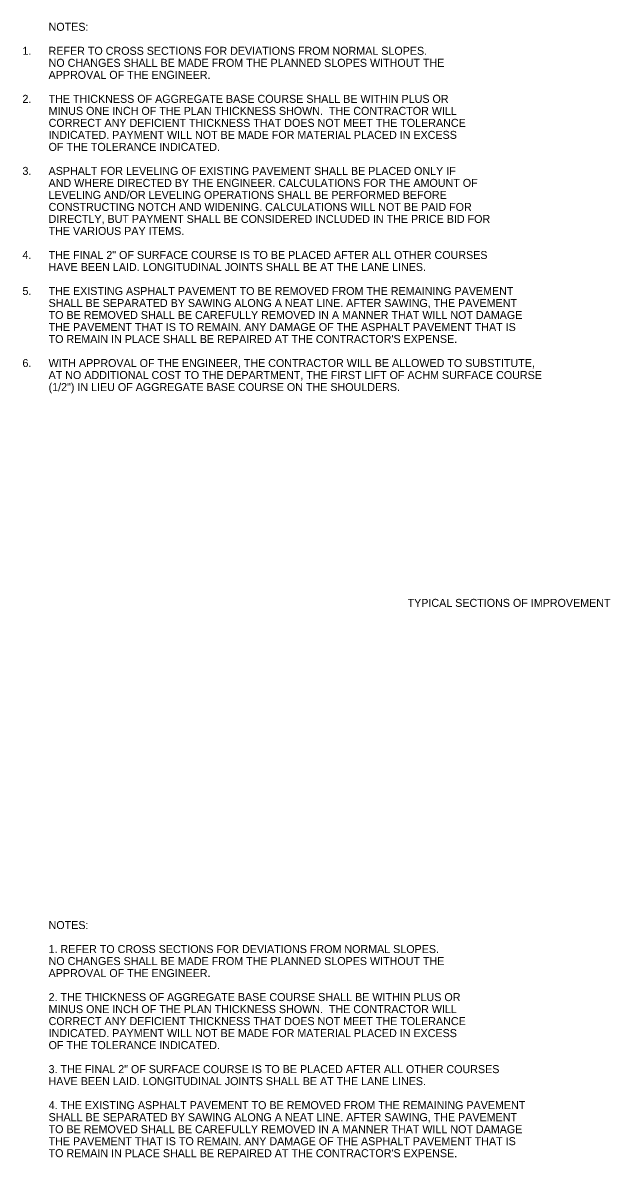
# Model space of a CAD drawing. Extents: x 138 to 3619, y -519 to 1449.
# Drawn here: x 1197 to 1637, y 598 to 1449 of the extents above; entities that cross this region are included whole.
import ezdxf

# ---------------------------------------------------------------- set-up
doc = ezdxf.new("R2010")
doc.units = 0
doc.layers.add('R_Annotation', color=7, linetype='Continuous')
doc.layers.add('R_Border', color=7, linetype='Continuous')

msp = doc.modelspace()

# ---------------------------------------------------------------- texts
at = {"layer": 'R_Annotation'}
for s, p in [('NOTES:', (1216.67, 1442.52)), ('1.', (1197.09, 1424.52)), ('REFER TO CROSS SECTIONS FOR DEVIATIONS FROM NORMAL SLOPES. ', (1216.67, 1424.52)), ('NO CHANGES SHALL BE MADE FROM THE PLANNED SLOPES WITHOUT THE', (1216.67, 1415.52)), ('APPROVAL OF THE ENGINEER.', (1216.67, 1406.52)), ('2.', (1197.09, 1388.52)), ('THE THICKNESS OF AGGREGATE BASE COURSE SHALL BE WITHIN PLUS OR', (1216.67, 1388.52)), ('MINUS ONE INCH OF THE PLAN THICKNESS SHOWN.  THE CONTRACTOR WILL', (1216.67, 1379.52)), ('CORRECT ANY DEFICIENT THICKNESS THAT DOES NOT MEET THE TOLERANCE', (1216.67, 1370.52)), ('INDICATED. PAYMENT WILL NOT BE MADE FOR MATERIAL PLACED IN EXCESS', (1216.67, 1361.52)), ('OF THE TOLERANCE INDICATED.', (1216.67, 1352.52)), ('3.', (1197.09, 1334.52)), ('ASPHALT FOR LEVELING OF EXISTING PAVEMENT SHALL BE PLACED ONLY IF', (1216.67, 1334.52)), ('AND WHERE DIRECTED BY THE ENGINEER. CALCULATIONS FOR THE AMOUNT OF', (1216.67, 1325.52)), ('LEVELING AND/OR LEVELING OPERATIONS SHALL BE PERFORMED BEFORE', (1216.67, 1316.52)), ('CONSTRUCTING NOTCH AND WIDENING. CALCULATIONS WILL NOT BE PAID FOR', (1216.67, 1307.52)), ('DIRECTLY, BUT PAYMENT SHALL BE CONSIDERED INCLUDED IN THE PRICE BID FOR', (1216.67, 1298.52)), ('THE VARIOUS PAY ITEMS.', (1216.67, 1289.52)), ('4.', (1197.09, 1271.52)), ('THE FINAL 2" OF SURFACE COURSE IS TO BE PLACED AFTER ALL OTHER COURSES', (1216.67, 1271.52)), ('HAVE BEEN LAID. LONGITUDINAL JOINTS SHALL BE AT THE LANE LINES.', (1216.67, 1262.52)), ('5.', (1197.09, 1244.52)), ('THE EXISTING ASPHALT PAVEMENT TO BE REMOVED FROM THE REMAINING PAVEMENT', (1216.67, 1244.52)), ('SHALL BE SEPARATED BY SAWING ALONG A NEAT LINE. AFTER SAWING, THE PAVEMENT', (1216.67, 1235.52)), ('TO BE REMOVED SHALL BE CAREFULLY REMOVED IN A MANNER THAT WILL NOT DAMAGE', (1216.67, 1226.52)), ('THE PAVEMENT THAT IS TO REMAIN. ANY DAMAGE OF THE ASPHALT PAVEMENT THAT IS', (1216.67, 1217.52)), ("TO REMAIN IN PLACE SHALL BE REPAIRED AT THE CONTRACTOR'S EXPENSE.", (1216.67, 1208.52)), ('6.', (1197.09, 1190.52)), ('WITH APPROVAL OF THE ENGINEER, THE CONTRACTOR WILL BE ALLOWED TO SUBSTITUTE,', (1216.67, 1190.52)), ('AT NO ADDITIONAL COST TO THE DEPARTMENT, THE FIRST LIFT OF ACHM SURFACE COURSE', (1216.67, 1181.52)), ('(1/2") IN LIEU OF AGGREGATE BASE COURSE ON THE SHOULDERS.', (1216.67, 1172.52)), ('NOTES:', (1216.67, 769.3)), ('1. REFER TO CROSS SECTIONS FOR DEVIATIONS FROM NORMAL SLOPES. ', (1216.67, 751.3)), ('NO CHANGES SHALL BE MADE FROM THE PLANNED SLOPES WITHOUT THE', (1216.67, 742.3)), ('APPROVAL OF THE ENGINEER.', (1216.67, 733.3)), ('2. THE THICKNESS OF AGGREGATE BASE COURSE SHALL BE WITHIN PLUS OR', (1216.67, 715.3)), ('MINUS ONE INCH OF THE PLAN THICKNESS SHOWN.  THE CONTRACTOR WILL', (1216.67, 706.3)), ('CORRECT ANY DEFICIENT THICKNESS THAT DOES NOT MEET THE TOLERANCE', (1216.67, 697.3)), ('INDICATED. PAYMENT WILL NOT BE MADE FOR MATERIAL PLACED IN EXCESS', (1216.67, 688.3)), ('OF THE TOLERANCE INDICATED.', (1216.67, 679.3)), ('3. THE FINAL 2" OF SURFACE COURSE IS TO BE PLACED AFTER ALL OTHER COURSES', (1216.67, 661.3)), ('HAVE BEEN LAID. LONGITUDINAL JOINTS SHALL BE AT THE LANE LINES.', (1216.67, 652.3)), ('4. THE EXISTING ASPHALT PAVEMENT TO BE REMOVED FROM THE REMAINING PAVEMENT', (1216.67, 634.3)), ('SHALL BE SEPARATED BY SAWING ALONG A NEAT LINE. AFTER SAWING, THE PAVEMENT', (1216.67, 625.3)), ('TO BE REMOVED SHALL BE CAREFULLY REMOVED IN A MANNER THAT WILL NOT DAMAGE', (1216.67, 616.3)), ('THE PAVEMENT THAT IS TO REMAIN. ANY DAMAGE OF THE ASPHALT PAVEMENT THAT IS', (1216.67, 607.3)), ("TO REMAIN IN PLACE SHALL BE REPAIRED AT THE CONTRACTOR'S EXPENSE.", (1216.67, 598.3))]:
    msp.add_text(s, height=6, dxfattribs=at).set_placement(p)
at = {"layer": 'R_Border'}
msp.add_text('TYPICAL SECTIONS OF IMPROVEMENT', height=6, dxfattribs=at).set_placement((1485.59, 1010.75))

doc.saveas('drawing.dxf')
